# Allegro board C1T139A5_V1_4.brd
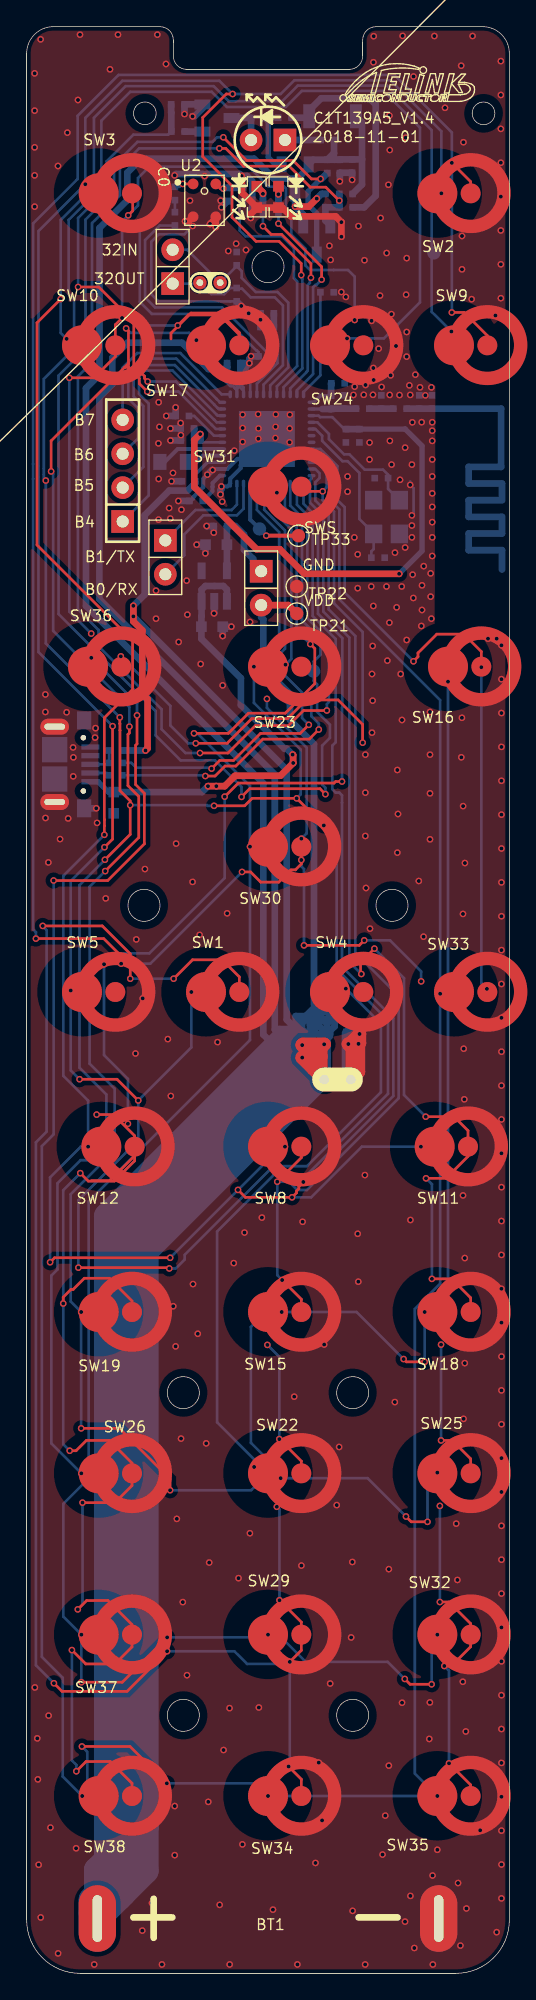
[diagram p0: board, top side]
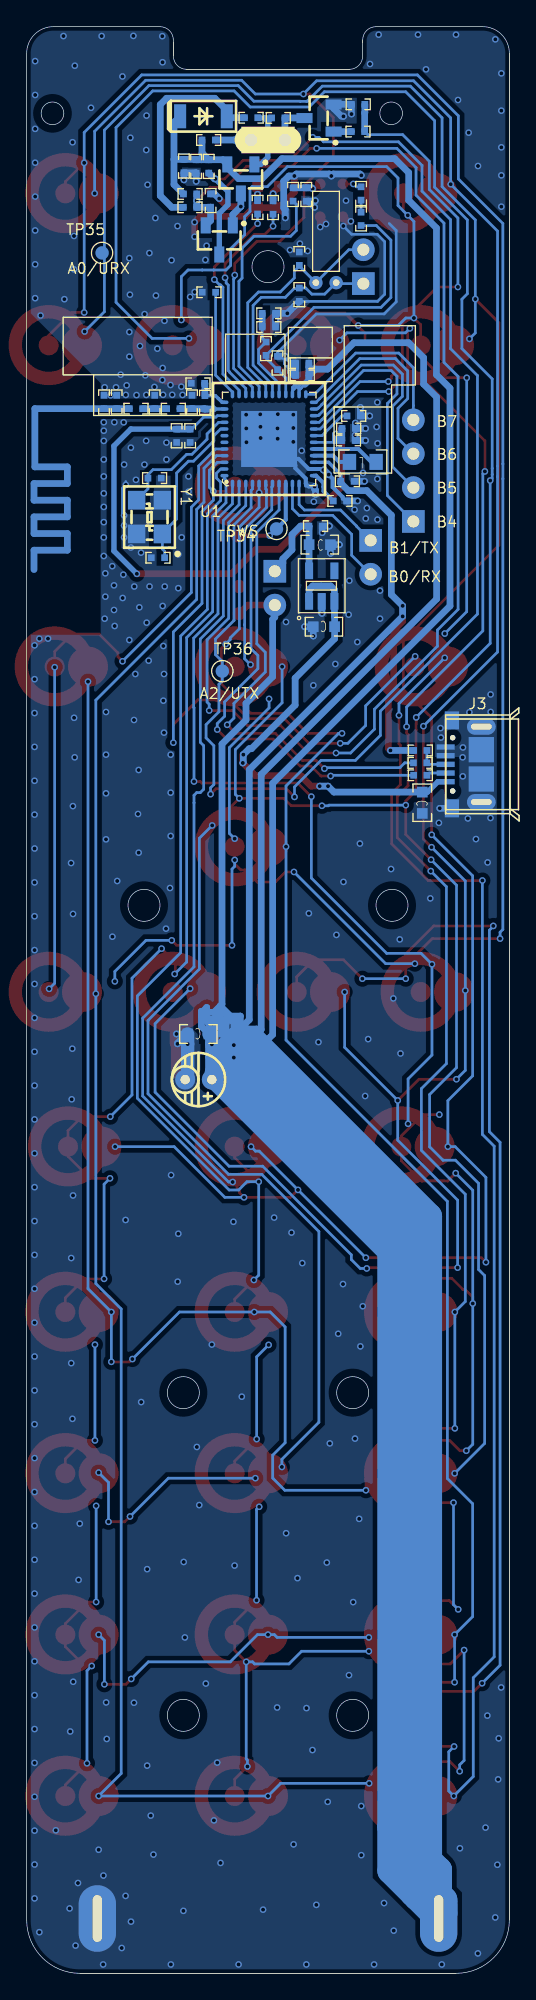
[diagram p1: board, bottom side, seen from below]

Outline 36.2 x 146 mm; copper layers: TOP, BOTTOM. Coordinates in mm from the lower left corner of the outline.
Outline path: circle c8.8,80.1 r1.2 ; circle c8.86,139.5 r0.85 ; circle c11.75,43.55 r1.2 ; circle c11.75,19.35 r1.2 ; circle c18.1,128 r1.2 ; circle c24.45,43.55 r1.2 ; circle c24.45,19.35 r1.2 ; circle c27.4,80.1 r1.2 ; circle c34.26,139.5 r0.85 ; 0,144 0,4 ; 0,144 arc(0.59,145.41) 2,146 10,146 arc(10.71,145.71) 11,145 ; 0,144 0,4 ; 0,4 arc(1.17,1.17) 4,0 ; 4,0 32.2,0 ; 4,0 32.2,0 ; 32.2,0 arc(35.03,1.17) 36.2,4 36.2,144 arc(35.61,145.41) 34.2,146 26.2,146 arc(25.49,145.71) 25.2,145 25.2,144.8 ; 11,145 11,144.8 ; 11,145 11,144.8 ; 11,144.8 11,143.8 arc(11.29,143.09) 12,142.8 ; 12,142.8 24.2,142.8 ; 12,142.8 24.2,142.8 ; 24.2,142.8 arc(24.91,143.09) 25.2,143.8 ; 25.2,144.8 25.2,143.8 ; 25.2,144.8 25.2,143.8

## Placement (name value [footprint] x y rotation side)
BT1  3V_2xAAA  [BAT_2DIP]  18.1 4.11 0 top
C1  0.1uF  [0402]  23.94 115.32 90 bottom
C2  2.2uF  [0402]  24.95 115.32 90 bottom
C4  1uF  [0402]  22.53 126.08 0 bottom
C7  1uF  [0402]  15.53 120.77 180 bottom
C8  1uF  [0402]  12.71 110.43 0 bottom
C10  1uF  [0402]  11.67 116.8 0 bottom
C12  4.7uF  [0402]  24.41 135.55 270 bottom
C13  4.7uF  [0402]  15.23 133.41 270 bottom
C16  10uF  [0603C]  23.33 70.45 0 bottom
C17  10pF  [0402]  17.39 120.78 90 bottom
C18  1uF  [0402]  11.12 133.49 90 bottom
C19  NC  [0402]  26.61 112.14 0 bottom
C20  NC  [0402]  26.35 106.17 180 bottom
C21  NC  [0402]  15.75 128.6 270 bottom
C22  NC  [0402]  15.75 125.9 90 bottom
C23  10pF  [0402]  18.04 123.48 180 bottom
C24  1uF  [0402]  18.04 124.5 180 bottom
C25  1uF  [0402]  12.06 114.96 180 bottom
C26  0.1uF  [0402]  23.49 135.52 270 bottom
C27  1uF  [0402]  12.14 111.91 0 bottom
C28  1uF  [0402]  15.53 119.84 180 bottom
C29  0.1uF  [0402]  12.05 115.86 0 bottom
C30  2.7pF  [0402C]  23.8 117.85 270 bottom
C31  18pF  [0402]  23.35 119.25 0 bottom
C32  2.2pF  [0402C]  26.6 117.85 270 bottom
C33  220pF  [0402C]  25.2 117.35 0 bottom
C34  1.5pF  [0402C]  29.45 117.85 270 bottom
C35  1.2pF  [0402]  30.4 117.85 270 bottom
C39  NC/10uF  [0603C]  13.9 101 0 bottom
C40  NC/10uF  [0603C]  14.22 107.15 180 bottom
C41  NC/0.1uF  [0402]  14.53 108.54 180 bottom
C42  NC/10uF  [0603C]  6.53 87.79 270 bottom
CD1  220uF/10V  [CD2P0_4P0B]  23.31 67.03 0 bottom
D1  Red_LED  [0603-LED]  17.25 133.23 270 top
D2  Red_LED  [0603-LED]  18.89 133.23 270 top
D4  1N4148  [SOD80]  22.94 139.28 180 bottom
D5  LED  [LED_TH_2P54MM_2PIN]  18.1 137.5 0 top
J3  NC/USB_MiniABF  [MICROUSB_DIP]  4.78 89.37 90 bottom
J5  NC/HEADER 4  [HDR254F-1X4X850]  7.2 116.51 270 top
J9  NC/HEADER 2  [HDR254F-1X2X850]  10.4 104.93 90 top
J10  HEADER 2  [HDR254F-1X2X850]  10.95 129.27 270 top
J36  NC/2PIN  [HDR254F-1X2X850]  17.59 102.62 90 top
L3  47UH  [0805L]  10.99 113.36 0 bottom
L4  1.3nH  [0402C]  22.83 117.82 270 bottom
L7  1.5nH  [0402C]  28 117.35 0 bottom
Q2  C1815  [SOT-23]  14.27 139.15 90 bottom
Q3  A1015  [SOT-23]  20.14 134.58 0 bottom
Q4  C1815  [SOT-23]  21.76 130 0 bottom
R1  1K  [0402]  18.88 132.45 90 bottom
R2  1K  [0402]  17.72 132.44 90 bottom
R3  0R  [0402]  16.22 133.41 90 bottom
R4  NC/1.5K  [0402]  6.68 91.71 0 bottom
R7  1  [0402]  22.55 137.5 0 bottom
R8  NC  [0402]  11.34 140.17 180 bottom
R9  100  [0402]  11.35 138.13 0 bottom
R10  10K  [0402]  22.54 135.52 90 bottom
R11  10K  [0402]  22.41 132.96 90 bottom
R12  NC  [0402]  23.94 133.45 180 bottom
R13  47K  [0402]  23.95 132.45 180 bottom
R14  22K  [0402]  19.37 139.17 0 bottom
R15  10K  [0402]  17.33 139.16 0 bottom
R16  NC  [0402]  18.25 121.85 90 bottom
R17  000R  [0402]  11.12 131.59 90 bottom
R69  NC/33  [0402]  6.69 90.79 180 bottom
R70  NC/33  [0402]  6.68 89.86 180 bottom
SW1  SW2PIN  [SW_OUT6_IN3]  13.45 73.6 180 top
SW2  SW2PIN  [SW_OUT6_IN3]  30.8 133.5 180 top
SW3  SW2PIN  [SW_OUT6_IN3]  5.4 133.5 180 top
SW4  SW2PIN  [SW_OUT6_IN3]  22.75 73.6 180 top
SW5  SW2PIN  [SW_OUT6_IN3]  4.15 73.6 180 top
SW8  SW2PIN  [SW_OUT6_IN3]  18.1 62 180 top
SW9  SW2PIN  [SW_OUT6_IN3]  32.05 122.1 180 top
SW10  SW2PIN  [SW_OUT6_IN3]  4.15 122.1 180 top
SW11  SW2PIN  [SW_OUT6_IN3]  30.6 62 180 top
SW12  SW2PIN  [SW_OUT6_IN3]  5.6 62 180 top
SW15  SW2PIN  [SW_OUT6_IN3]  18.1 49.6 180 top
SW16  SW2PIN  [SW_OUT6_IN3]  31.6 98 180 top
SW17  SW2PIN  [SW_OUT6_IN3]  13.45 122.1 180 top
SW18  SW2PIN  [SW_OUT6_IN3]  30.8 49.6 180 top
SW19  SW2PIN  [SW_OUT6_IN3]  5.4 49.6 180 top
SW22  SW2PIN  [SW_OUT6_IN3]  18.1 37.5 180 top
SW23  SW2PIN  [SW_OUT6_IN3]  18.1 98 180 top
SW24  SW2PIN  [SW_OUT6_IN3]  22.75 122.1 180 top
SW25  SW2PIN  [SW_OUT6_IN3]  30.8 37.5 180 top
SW26  SW2PIN  [SW_OUT6_IN3]  5.4 37.5 180 top
SW29  SW2PIN  [SW_OUT6_IN3]  18.1 25.4 180 top
SW30  SW2PIN  [SW_OUT6_IN3]  18.1 84.5 180 top
SW31  SW2PIN  [SW_OUT6_IN3]  18.1 111.5 180 top
SW32  SW2PIN  [SW_OUT6_IN3]  30.8 25.4 180 top
SW33  SW2PIN  [SW_OUT6_IN3]  32.05 73.6 180 top
SW34  SW2PIN  [SW_OUT6_IN3]  18.1 13.3 180 top
SW35  SW2PIN  [SW_OUT6_IN3]  30.8 13.3 180 top
SW36  SW2PIN  [SW_OUT6_IN3]  4.6 98 180 top
SW37  SW2PIN  [SW_OUT6_IN3]  5.4 25.4 180 top
SW38  SW2PIN  [SW_OUT6_IN3]  5.4 13.3 180 top
TP21  VDD  [TP100]  20.26 101.98 0 top
TP22  GND  [TP100]  20.26 104.01 0 top
TP33  SWS  [TP100]  20.38 107.82 0 top
TP34  SWS  [TP100]  17.46 108.33 180 bottom
TP35  URX  [TP100]  30.54 129.03 180 bottom
TP36  UTX  [TP100]  21.53 97.66 180 bottom
U1  TLSR8258F512ET48  [QFN_7X7_48PIN_0P5_4P20X4P20]  18.02 115.08 90 bottom
U2  GA-BFA423-A83-1  [GA_BFA423_A83]  13.33 132.97 0 top
U5  NC/XC6219_3.3V_SOT-23-5  [SOT-23-5]  14.07 104.04 180 bottom
Y1  24MHz-12pF-+/-20ppm  [OSCCC250X320X110]  26.99 109.22 0 bottom
Y2  NC/32.768KHz - 9pf - +/-20ppm  [OSC_2X6]  13.75 130.8 270 bottom

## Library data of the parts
BT1 = BATTERY_2xAAA_3V
C1 C26 C41 = C1005X5R1C104K
C2 = C1005X5R1A225K
C4 C8 = C1005X5R1C105K
C7 = C1608X5R1C105M_0
C10 = C1005X5R1C105K_0
C12 = C1608X5R1A226M
C13 C17 C18 C23-C25 = C1608X5R0J475M
C16 = C1608X5R0J106M
C19-C22 C30 C32-C34 = C1608_NC
C27 C29 = C1005X5R1C105K_1
C28 = C1005X5R1C105K_2
C31 = C1005C0G1H100D
C35 = C1005_NC
C39 C40 C42 = C1608X5R1A106K
CD1 = CD_220uF_16V
D1 D2 = 0603D_Red
D4 = Diode_1N4148
D5 = Led_Th_3mm_1: User Part Number: partnum; Tolerance: RichardLC
J3 = USB_MiniABF_2
J5 = HEADER 4: User Part Number: pn; Tolerance: RichardLC
J9 J10 = HEADER 2: User Part Number: pn; Tolerance: RichardLC
J36 = B2S_2: User Part Number: pn; Tolerance: RichardLC
L3 = IND_0
L4 L7 = MLK1608_000R
Q2 Q4 = NPN_C1815
Q3 = PNP_A1015
R1-R4 R16 R17 = RS0402K472JT
R7 = RS0805K1R0JT
R8 R12 = RS0402_NC
R9 = RS0402K101JT
R10 R11 R15 = RS0402K103JT
R13 = RS0402K473JT
R14 = RS0402K223JT
R69 R70 = RS0402K330JT
SW1-SW5 SW8-SW12 SW15-SW19 SW22-SW26 SW29-SW38 = SW2PIN_0
TP21 TP22 TP33-TP36 = TestPad100
U1 = TLSR8258F512ET48
U2 = MULPS4CX-RM5_0
U5 = XC6219_1.3V_SOT-23-5
Y1 = CRYSTAL4/SM_0: Tolerance: RichardLC
Y2 = OSC_2x6_2pin_16Mhz

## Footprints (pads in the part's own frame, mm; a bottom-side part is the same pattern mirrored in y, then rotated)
0402
  rect 0.5x0.5 smd: 1(-0.5,0) 2(0.5,0)
0402C
  rect 0.5x0.5 smd: 1(-0.5,0) 2(0.5,0)
0603-LED
  rect 0.8x0.8 smd: A(-0.8,0) C(0.8,0)
0603C
  rect 0.8x0.8 smd: 1(-0.8,0) 2(0.8,0)
0805L
  rect 1x1.2 smd: 1(-1,0) 2(1,0)
BAT_2DIP
  oval 2.8x5 hole 0.7x3.5: 1(-12.8,0) 2(12.8,0)
CD2P0_4P0B
  round 1.5 hole 0.7: 1(-1,0) 2(1,0)
GA_BFA423_A83
  round 0.8 smd: 1(-0.85,1.23) 2(-0.85,-1.23) 3(0.85,-1.23) 4(0.85,1.23)
HDR254F-1X2X850
  rect 1.7x1.7 hole 0.9: 1(2.54,0)
  round 1.7 hole 0.9: 2(0,0)
HDR254F-1X4X850
  rect 1.7x1.7 hole 0.9: 1(7.62,0)
  round 1.7 hole 0.9: 2(5.08,0) 3(2.54,0) 4(0,0)
LED_TH_2P54MM_2PIN
  rect 1.7x1.7 hole 0.9: A(1.27,0)
  round 1.7 hole 0.9: C(-1.27,0)
MICROUSB_DIP
  round 0.4 hole 0.6 unplated: (-0.7,-0.525) (3.3,-0.525)
  rect 0.4x1.35 smd: 1(0,0) 2(0.65,0) 3(1.3,0) 4(1.95,0) 5(2.6,0)
  oval 1.2x2.15 hole 0.45x1.55: 6(-1.525,-2.675) 7(4.125,-2.675)
  rect 1.9x1.9 smd: 8(0.2,-2.675) 9(2.4,-2.675)
  rect 1.35x1.07 smd: 10(-1.996,-0.468) 11(4.596,-0.468)
OSC_2X6
  round 1 hole 0.5: 1(4,0.76) 2(4,-0.76)
OSCCC250X320X110
  rect 1.3x1.4 smd: 1(-0.965,1.265) 2(-0.965,-1.265) 3(0.965,-1.265) 4(0.965,1.265)
QFN_7X7_48PIN_0P5_4P20X4P20
  oval 0.6x0.26 smd: 1(-3.35,2.75) 2(-3.35,2.25) 3(-3.35,1.75) 4(-3.35,1.25) 5(-3.35,0.75) 6(-3.35,0.25) 7(-3.35,-0.25) 8(-3.35,-0.75) 9(-3.35,-1.25) 10(-3.35,-1.75) 11(-3.35,-2.25) 12(-3.35,-2.75) 25(3.35,-2.75) 26(3.35,-2.25) 27(3.35,-1.75) 28(3.35,-1.25) 29(3.35,-0.75) 30(3.35,-0.25) 31(3.35,0.25) 32(3.35,0.75) 33(3.35,1.25) 34(3.35,1.75) 35(3.35,2.25) 36(3.35,2.75)
  oval 0.26x0.6 smd: 13(-2.75,-3.35) 14(-2.25,-3.35) 15(-1.75,-3.35) 16(-1.25,-3.35) 17(-0.75,-3.35) 18(-0.25,-3.35) 19(0.25,-3.35) 20(0.75,-3.35) 21(1.25,-3.35) 22(1.75,-3.35) 23(2.25,-3.35) 24(2.75,-3.35) 37(2.75,3.35) 38(2.25,3.35) 39(1.75,3.35) 40(1.25,3.35) 41(0.75,3.35) 42(0.25,3.35) 43(-0.25,3.35) 44(-0.75,3.35) 45(-1.25,3.35) 46(-1.75,3.35) 47(-2.25,3.35) 48(-2.75,3.35)
  rect 4.2x4.2 smd: 49(0,0)
SOD80
  rect 0.9x1.8 smd: A(-1.75,0) C(1.75,0)
SOT-23
  rect 0.75x1.2 smd: 1(-1.016,-1.092) 2(1.016,-1.092) 3(0,1.092)
SOT-23-5
  rect 0.6x1.25 smd: 1(-0.95,-1.145) 2(0,-1.145) 3(0.95,-1.145) 4(0.95,1.145) 5(-0.95,1.145)
SW_OUT6_IN3
  round 3 smd: 1(0,0)
  custom 1.5x1.5 smd: 2(-2.5,0)
TP100
  round 1 smd: 1(0,0)

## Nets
GND: BT1.2(-) C1.1 C2.1 C4.2 C7.1 C8.1 C10.1 C12.2 C13.2 C16.2 C17.2 C19.1 C20.1 C21.1 C22.1 C23.2 C24.2 C25.2 C26.2 C27.1 C28.1 C29.1 C30.1 C31.2 C32.1 C34.1 C35.1 C39.2 C40.2 C41.2 C42.2 CD1.2 D1.C(CATHODE) D2.C(CATHODE) J3.4(ID) J3.5(GND) J3.6(S1) J3.7(S2) J3.8(S3) J3.9(S4) J3.10(S5) J3.11(S6) Q2.2(E) R8.1 TP22.1(TP) U1.12(DVSS#12) U1.14(DVSS#14) U1.49(GND) U2.2(GND#2) U2.3(GND#3) U5.2(VSS) Y1.2 Y1.4
VDD1V2: C1.2 C2.2 C25.1 C29.2 U1.18(VDD1V2) U1.39(AVDD1V2)
TL_32INPUT: C21.2 J10.2 U1.31(P1/URX/I2CCK/32KI/PGAN1/C[3]) Y2.2
TL_32OUTPUT: C22.2 J10.1 U1.30(P0/7816TRX/I2CSDA/32KO/PGAP1/C[) Y2.1
TL_AMICBIAS: R3.1 U1.32(P2/UCTS/P0N/BIAS/C[4])
TL_AMICSN: C23.1 C24.1 R16.2 U1.29(I2CCK/P1N/P0/PGAN0/C[1])
TL_AMICSP: C17.1 R16.1 R17.1 U1.28(I2CSDA/P4N/URTS/PGAP0/C[0])
TL_B0: J9.2 U1.10(P3/URX/ATSEL1/B[0])
TL_B1: J9.1 U1.11(P4/UTX/ATSEL2/B[1])
TL_B4: J5.1 U1.22(SDMP0/P4/B[4])
TL_B5: J5.2 U1.23(SDMN0/P5/B[5])
TL_B6: J5.3 U1.24(SDMP1/DI/URTS/B[6])
TL_B7: J5.4 U1.25(SDMN1/DO/URX/B[7])
TL_COL0: SW1.1 SW2.1 SW3.1 SW4.1 SW5.1 U1.33(P3N/URX/ATSEL0/C[5])
TL_COL1: SW8.1 SW9.1 SW10.1 SW11.1 SW12.1 TP35.1(TP) U1.2(DMIC_DI/P0N/URX/A[0])
TL_COL2: SW15.1 SW16.1 SW17.1 SW18.1 SW19.1 U1.20(P5/UCTS/CYC2LNA/B[2])
TL_COL3: SW22.1 SW23.1 SW24.1 SW25.1 SW26.1 U1.6(CK/URTS/P2/A[4])
TL_COL4: SW29.1 SW30.1 SW31.1 SW32.1 SW37.1 U1.5(DI/UCTS/P1/A[3])
TL_COL5: SW33.1 SW34.1 SW35.1 SW36.1 SW38.1 U1.45(P1N/I2SSDI/7816TRX/D[3])
TL_DM: R70.1 U1.7(DM/A[5])
TL_DP: R69.1 U1.8(DP/A[6])
TL_IRCONTROL: Q4.2(E) R11.1 R12.2 R13.2 U1.3(DMIC_CK/7816CLK/I2SCK/A[1])
TL_IRIN: Q4.3(C) R10.1 TP36.1(TP) U1.4(DO/UTX/P0/A[2])
TL_IROUT: R8.2 R9.1 U1.21(P0N/URTS/CYC2PA/B[3])
TL_LED1: R2.1 U1.34(CYC2LNA/ATSEL1/P4N/C[6])
TL_LED2: R1.1 U1.35(CYC2PA/ATSEL2/P5N/C[7])
TL_ROW0: SW1.2 SW8.2 SW15.2 SW22.2 SW29.2 SW34.2 U1.47(P0/P0N/D[5])
TL_ROW1: SW2.2 SW9.2 SW16.2 SW23.2 SW30.2 SW33.2 U1.44(CN/I2SLR/P3/D[2])
TL_ROW2: SW3.2 SW10.2 SW17.2 SW24.2 SW31.2 SW36.2 U1.46(SWM/I2SSDO/P2N/D[4])
TL_ROW3: SW4.2 SW11.2 SW18.2 SW25.2 SW32.2 SW35.2 U1.48(CN/URX/ATSEL0/D[6])
TL_ROW4: SW5.2 SW12.2 SW19.2 SW26.2 SW37.2 SW38.2 U1.1(CK/I2SBCK/7816TRX/D[7])
TL_RST: C4.1 U1.36(RESETB)
TL_SWS: TP33.1(TP) TP34.1(TP) U1.9(SWS/URTS/A[7])
TL_VBUS: C39.1 C42.1 J3.1(V_BUS) U5.1(VIN) U5.3(CE)
TL_VDD: BT1.1(+) C7.2 C12.1 C16.1 C26.1 C27.2 C28.2 CD1.1 D4.A J36.2 Q3.2(E) R4.2 R7.2 R10.2 R12.1 TP21.1(TP) U1.15(VDD_IO) U1.26(VDD3) U1.27(VDDIO_AMS)
TL_XC1: C19.2 U1.40(XC1) Y1.3
TL_XC2: C20.2 U1.41(XC2) Y1.1
N21000893: D2.A(ANODE) R1.2
N21007782: D1.A(ANODE) R2.2
N21036936: C13.1 R3.2 U2.4(VDD)
N21036981: C18.1 R17.2
N21036983: C18.2 U2.1(OUTPUT)
N21081547: C40.1 C41.1 J36.1 U5.5(VOUT)
N21081898: J3.3(D+) R4.1 R69.2
N21081900: J3.2(D-) R70.2
N21088560: C10.2 U1.19(VDD_F)
N21088582: L3.1 U1.17(VDCDC)
N21088586: L3.2 U1.16(VDCDC_SW)
N21088616: C8.2 U1.13(VDD1V)
N21092386: C30.2 C33.1 L4.2 U1.38(ANT)
N21092388: C31.1 L4.1 U1.37(VANT)
N21092398: C32.2 C33.2 L7.1
N21092424: C34.2 C35.2 L7.2
N21108187: D5.A(ANODE) R7.1
N21108227: D4.C R13.1 R14.2
N21108333: Q2.1(B) R9.2
N21108349: D5.C(CATHODE) Q2.3(C) R15.1
N21108369: Q3.3(C) Q4.1(B) R11.2
N21108379: Q3.1(B) R14.1 R15.2

Pads without a net: U1 42 43; U5 4

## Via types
v1: diameter 0.5, hole 0.3, TOP to BOTTOM, 547 vias

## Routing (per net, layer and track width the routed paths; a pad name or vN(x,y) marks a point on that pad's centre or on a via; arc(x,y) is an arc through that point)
GND: length 124.3
  TOP w0.5: v1(13.75,131.2) 14.18,131.63 ; 14.18,131.63 v1(14.18,130.98) ; 14.18,131.63 U2.3 ; v1(23.61,130.24) v1(23.61,131.34) 23.18,131.77 19.84,131.77 19.17,132.43 D2.C D1.C ; v1(16.8,131.66) 16.8,131.93 17.25,132.39 D1.C ; v1(11.88,131.4) 12.14,131.4 U2.2 ; D1.C 17.25,132.45 16.12,133.58 v1(16.12,134.8)
  TOP w1: 24.41,67.13 24.89,67.61 v1(24.89,69.71) 24.97,69.79 v1(24.97,70.45) 24.21,69.7 v1(24.13,69.7) 24.41,69.41 24.41,67.13 ; 24.41,67.13 CD1.2
  BOTTOM w0.2: U1.49 18.1,115.15 v1(18.66,115.15) ; U1.49 17.2,114.86 v1(16.2,114.86) ; U1.49 17.45,115.87 v1(17.39,115.87) ; U1.49 19.57,115.7 v1(19.73,115.87) ; U1.49 18.02,116.28 v1(17.36,116.94) ; U1.49 16.85,116.9 v1(16.2,116.9) ; U1.49 19.21,114.83 v1(19.72,114.83) ; U1.49 18.67,115.85 v1(18.67,115.99) ; U1.49 19.6,116.9 v1(19.74,116.9) ; U1.49 18.64,116.88 v1(18.68,116.92) ; C17.2 17.39,121.59 17.25,121.73 17.21,121.73 14.49,124.45 9.39,124.45 8.48,125.36 8.48,130.71 9.01,131.24 ; 28.77,111.89 v1(28.77,111.63) 29.02,111.38 29.02,109.47 v1(28.89,109.35) ; v1(12.45,131.05) 11.83,130.43 9.91,130.43 9.35,129.87 9.35,125.93 9.89,125.4 15.27,125.4 15.27,125.4 C22.1
  BOTTOM w0.25: 14.08,112.83 13.95,112.7
  BOTTOM w0.3: 16.52,113.58 U1.49 ; 16.52,113.58 15.81,113.58 15.05,112.83 U1.14 14.03,112.83 v1(13.95,112.75) ; 16.52,113.58 16.05,113.11 16.05,112.89 15.27,112.1 U1.12 15.05,111.51 v1(14.6,111.51) ; 12.49,110.59 12.49,110.72 13.24,111.46 13.24,112.09 v1(13.55,112.4)
  BOTTOM w0.5: v1(24.89,69.71) 24.89,69.75 24.19,70.45 ; 15.06,132.91 14.59,132.91 v1(14.55,132.95) ; 15.06,132.91 C13.2 ; 15.06,132.91 v1(14.6,132.45) ; v1(14.03,108.05) C41.2 13.51,108.54 v1(13.5,108.55) ; v1(14.7,100.3) 14.7,100.3 C39.2 15.35,101 v1(15.35,101) ; 16.41,120.11 16.03,120.48 ; 16.41,120.11 16.41,120.47 v1(16.7,120.76) ; 16.41,120.11 16.14,119.84 C28.1 16.03,120.48 ; 16.03,120.48 C7.1 16.69,120.77 v1(16.7,120.76) ; v1(14.6,111.51) 14.6,111.3 14.53,111.23 v1(14.53,110.92) ; v1(10.78,114.96) C25.2 v1(11.56,115.36) ; v1(12.75,107.15) 12.75,107.15 C40.2 13.42,106.52 v1(13.4,106.5) ; v1(12.44,139.27) 12.46,139.29 12.6,139.29 13.18,139.87 Q2.2 13.17,140.17 R8.1 v1(11.84,139.45) ; v1(5.22,87.38) J3.10 ; U5.2 14.07,102.02 v1(14.05,102) ; 24.19,70.45 v1(24.97,70.45) ; 24.19,70.45 C16.2 ; v1(13.95,112.75) 13.9,112.75 v1(13.55,112.4) ; v1(24.41,134.51) C12.2 23.52,135.05 C26.2 v1(23.49,134.4) ; v1(10.78,115.86) C29.1 v1(11.55,116.27) ; C8.1 v1(11.38,110.43) ; v1(11.1,134.85) 11.2,134.95 13.2,134.95 v1(13.35,134.8) 13.5,134.95 15.97,134.95 v1(16.12,134.8) 16.53,134.8 16.92,134.41 16.92,132.41 16.8,132.29 v1(16.8,131.66) ; v1(11.17,117.44) C10.1 v1(10.47,116.8) ; v1(16.7,120.76) 16.7,121.08 16.89,121.28 C17.2 ; C23.2 v1(17.54,124.02) C24.2 v1(16.65,124.5) v1(16.1,125.05) C22.1 ; C27.1 v1(10.86,111.91)
  BOTTOM w1: C16.2 v1(24.13,69.7) 24.13,67.22 CD1.2
  vias: v1(0.6,142.5) v1(0.6,139.7) v1(0.6,136.95) v1(0.6,134.85) v1(0.6,132.5) v1(0.62,21.44) v1(0.8,17.62) v1(0.84,14.55) v1(0.9,8.14) v1(1.05,145.05) v1(1.06,4.19) v1(1.4,95.92) v1(1.4,94.6) v1(1.41,86.65) v1(1.63,83.32) v1(1.65,19.33) v1(1.78,10.93) v1(2.35,135.55) v1(2.36,1.5) v1(2.5,85.07) v1(3,94.58) v1(3.05,138.05) v1(3.11,86.62) v1(3.48,91.94) v1(3.5,91.2) v1(3.49,89.77) v1(3.71,9.38) v1(3.85,140.5) v1(4,145.4) v1(5.13,92.68) v1(5.07,0.67) v1(5.16,93.39) v1(5.28,86.28) v1(5.93,80.62) v1(6.25,142.8) v1(6.85,145.4) v1(8.22,77.54) v1(8.16,68.99) v1(8.7,73.12) v1(8.67,3.2) v1(8.87,82.82) v1(9.4,5.27) v1(9.7,103.7) v1(9.7,101.6) v1(9.8,145.4) v1(9.9,117.83) v1(9.88,114.75) v1(9.9,112.08) v1(9.89,109.03) v1(9.96,115.98) v1(10.15,0.67) v1(10.45,143.2) v1(10.59,70.07) v1(10.68,109.89) v1(10.77,109.11) v1(10.81,65.8) v1(10.97,112.53) v1(10.99,50.03) v1(11.1,12.55) v1(11.1,8.86) v1(11.21,84.73) v1(11.17,47.02) v1(11.26,34.09) v1(11.4,99.85) v1(11.61,109.77) v1(11.58,40.11) v1(11.71,27.84) v1(12,104.45) v1(12.03,22.36) v1(12.05,101.9) v1(12.25,132.95) v1(12.44,81.86) v1(12.48,51.69) v1(12.83,47.97) v1(12.97,77.88) v1(13.05,98.2) v1(13.46,39.75) v1(13.62,12.86) v1(13.69,30.81) v1(14.32,69.84) v1(14.47,5.14) v1(14.66,110.38) v1(14.7,96.6) v1(14.77,16.75) v1(15.04,79.5) v1(15.12,129.18) v1(15.22,19.89) v1(15.23,0.67) v1(15.53,53.27) v1(15.57,114.2) v1(15.71,129.73) v1(15.89,29.64) v1(16.2,115.9) v1(16.18,9.67) v1(16.34,55.56) v1(16.45,129.25) v1(16.74,33.01) v1(16.83,121.28) v1(16.75,101.35) v1(17.38,115.09) v1(17.42,19.94) v1(17.64,56.68) v1(18.47,4.78) v1(20.07,43.25) v1(20.31,0.67) v1(20.61,30.58) v1(20.7,56.37) v1(21.66,8.28) v1(21.91,15.8) v1(22.16,11.47) v1(22.31,47.16) v1(22.71,129.56) v1(22.8,128.51) v1(22.76,21.73) v1(23.26,35.12) v1(23.44,39.48) v1(23.6,126.1) v1(23.94,125.73) v1(24.07,112.27) v1(24.07,111.12) v1(24.33,25.19) v1(24.42,30.85) v1(24.45,4.69) v1(24.51,118.38) v1(24.6,119) v1(24.57,107.7) v1(24.83,106.43) v1(24.83,103.89) v1(24.83,55.47) v1(24.89,131.04) v1(24.87,51.87) v1(25.33,128.48) v1(25.28,118.39) v1(25.41,119.13) v1(25.4,91.4) v1(25.4,88.55) v1(25.4,85.3) v1(25.45,81.4) v1(25.37,59.87) v1(25.39,0.67) v1(25.72,114.81) v1(25.72,113.54) v1(25.84,104.01) v1(25.75,78.35) v1(25.87,123.94) v1(25.95,99.55) v1(25.9,97.45) v1(25.95,95.45) v1(25.9,93.05) v1(26.03,145.28) v1(26.01,143.33) v1(26,120.4) v1(26.02,119.5) v1(25.97,118.39) v1(26,102.55) v1(26.4,121.85) v1(26.55,131.65) v1(26.5,125.83) v1(26.62,118.98) v1(26.69,8.91) v1(26.89,11.83) v1(27,129.02) v1(26.99,104.01) v1(27.13,134.14) v1(27.05,98.45) v1(27.21,139.33) v1(27.23,136.75) v1(27.23,118.38) v1(27.24,114.94) v1(27.2,101.3) v1(27.16,30.31) v1(27.16,15.58) v1(27.3,119.85) v1(27.36,124.44) v1(27.37,113.16) v1(27.62,106.55) v1(27.61,42.85) v1(27.7,122.05) v1(27.75,102.45) v1(27.8,90.25) v1(27.8,84.05) v1(27.85,86.95) v1(27.96,118.37) v1(28,112.01) v1(28.13,104.01) v1(28.05,97.45) v1(28.15,94) v1(28.2,145.31) v1(28.15,20.3) v1(28.42,137.67) v1(28.38,114.43) v1(28.38,106.93) v1(28.38,3.88) v1(28.5,128.64) v1(28.46,125.9) v1(28.5,123.1) v1(28.5,121.25) v1(28.5,100) v1(28.7,119.1) v1(28.77,118.38) v1(28.78,56.5) v1(28.78,5.81) v1(28.92,116.33) v1(28.89,113.16) v1(28.89,108.58) v1(28.89,107.7) v1(28.95,104.9) v1(29.02,142.26) v1(29,103.15) v1(29.15,119.9) v1(29.07,1.9) v1(29.41,81.93) v1(29.5,118.95) v1(29.62,116.34) v1(29.65,104.1) v1(29.65,102.25) v1(29.6,101.05) v1(29.78,105.54) v1(29.77,77.75) v1(29.9,118.35) v1(30.25,94.6) v1(30.25,91.4) v1(30.25,88.5) v1(30.25,85.05) v1(30.24,20.32) v1(30.2,17.58) v1(30.3,105) v1(30.3,103.25) v1(30.35,118.95) v1(30.42,116.33) v1(30.42,115.7) v1(30.42,114.94) v1(30.42,113.54) v1(30.42,112.27) v1(30.42,111) v1(30.42,109.98) v1(30.42,108.84) v1(30.42,107.7) v1(30.42,106.3) v1(30.35,101.6) v1(30.44,7.34) v1(30.47,0.67) v1(30.58,145.3) v1(30.8,9.27) v1(31.38,139.92) v1(32.22,33.73) v1(32.31,29.5) v1(32.35,6.77) v1(32.53,2.08) v1(32.59,143.07) v1(32.65,130.3) v1(32.65,127.8) v1(32.64,94.17) v1(32.6,91.2) v1(32.73,87.54) v1(32.72,79.45) v1(32.72,58.34) v1(32.71,21.87) v1(32.76,137.33) v1(32.78,69.35) v1(32.82,65.55) v1(32.77,41.59) v1(32.87,83.27) v1(32.86,53.65) v1(32.86,45.77) v1(32.94,18.14) v1(32.98,4.86) v1(33.44,145.3) v1(33.37,125.56) v1(34.01,10.73) v1(34.6,100.1) v1(35.16,124.34) v1(35.25,100.1) v1(35.25,3.09) v1(35.56,143.42) v1(35.56,140.88) v1(35.56,138.34) v1(35.56,135.8) v1(35.56,133.26) v1(35.56,130.72) v1(35.56,128.18) v1(35.56,125.64) v1(35.61,99.6) v1(35.61,97.06) v1(35.61,94.52) v1(35.61,91.98) v1(35.61,89.44) v1(35.61,86.9) v1(35.61,84.36) v1(35.61,81.82) v1(35.61,79.28) v1(35.61,76.74) v1(35.61,74.2) v1(35.61,71.66) v1(35.61,69.12) v1(35.61,66.58) v1(35.61,64.04) v1(35.61,61.5) v1(35.61,58.96) v1(35.61,56.42) v1(35.61,53.88) v1(35.61,51.34) v1(35.61,48.8) v1(35.61,46.26) v1(35.61,43.72) v1(35.61,41.18) v1(35.61,38.64) v1(35.61,36.1) v1(35.61,33.56) v1(35.61,31.02) v1(35.61,28.48) v1(35.61,25.94) v1(35.61,23.4) v1(35.61,20.86) v1(35.61,18.32) v1(35.61,15.78) v1(35.61,13.24) v1(35.61,10.7) v1(35.61,8.16) v1(35.61,5.62)
VDD1V2: length 45.3
  TOP w0.5: v1(13.02,115.44) 12.57,115 12.57,111.48 17.24,106.81 18.99,106.81 20.83,104.96 v1(27.94,104.96)
  BOTTOM w0.2: 13.04,114.96 13.18,114.83 U1.18 ; U1.39 21.89,116.83 22.01,116.71 22.92,116.71 23.82,115.82 C1.2
  BOTTOM w0.4: C2.2 28.38,115.82 28.38,115.82 29.65,114.55 29.65,106.68 v1(27.94,104.96)
  BOTTOM w0.5: v1(13.02,115.44) 13.04,115.42 13.04,114.96 C25.1 12.56,114.96 12.56,115.85 C29.2 ; C1.2 C2.2
TL_32INPUT: length 19.1
  BOTTOM w0.2: 15.75,128.04 Y2.2 12.04,129.27 J10.2 ; 15.75,128.04 16.13,127.66 16.13,127.15 17.18,126.1 18.81,126.1 19.62,125.3 19.62,120.44 18.27,119.09 U1.31 ; 15.75,128.04 C21.2
TL_32OUTPUT: length 16.7
  BOTTOM w0.2: U1.30 17.77,119.16 19.22,120.61 19.22,125.09 18.61,125.7 16.8,125.7 16.15,126.35 15.8,126.35 C22.2 15.27,126.4 14.81,125.94 13.85,125.94 Y2.1 12.92,126.73 J10.1
TL_AMICBIAS: length 18.6
  BOTTOM w0.2: U1.32 18.77,119.02 20.28,120.54 20.28,126.9 20.04,127.14 20.04,129.39 19.15,130.28 16.41,130.28 15.98,130.71 15.98,132.67 R3.1
TL_AMICSN: length 7.1
  BOTTOM w0.2: C23.1 18.54,122.64 R16.2 18.81,121.79 18.81,120.76 17.27,119.22 U1.29
  BOTTOM w0.5: C24.1 C23.1
TL_AMICSP: length 21.7
  BOTTOM w0.2: U1.28 16.77,119.66 C17.1 18.25,121.14 R16.1 14.66,124.94 9.63,124.94 8.88,125.69 8.88,129.99 9.98,131.09 R17.1
TL_B0: length 10.7
  BOTTOM w0.2: U1.10 16.27,109.85 15.77,109.35 13.25,109.35 11.82,107.92 11.82,106.35 J9.2
TL_B1: length 8.1
  BOTTOM w0.2: U1.11 15.77,110.15 15.37,109.75 12.66,109.75 11.45,108.54 11.45,108.52 J9.1
TL_B4: length 19.8
  BOTTOM w0.2: J5.1 9.15,110.84 9.15,117.73 8.43,118.46 8.43,119.78 8.86,120.21 10.94,120.21 14.22,116.93 14.22,116.93 14.32,116.83 U1.22
TL_B5: length 17.8
  BOTTOM w0.2: J5.2 8.75,112.98 8.75,117.54 8.02,118.27 8.02,119.94 8.7,120.62 11.11,120.62 14.07,117.66 14.07,117.65 14.32,117.4 14.33,117.4 14.4,117.33 U1.23
TL_B6: length 15.8
  BOTTOM w0.2: J5.3 8.35,115.12 8.35,117.38 7.62,118.11 7.62,120.18 8.55,121.11 11.22,121.11 14.24,118.08 14.24,118.08 14.5,117.83 U1.24
TL_B7: length 13.7
  BOTTOM w0.2: J5.4 7.2,117.59 7.2,117.59 7.2,120.42 8.29,121.52 11.53,121.52 14.62,118.43 U1.25
TL_COL0: length 212.2
  TOP w0.2: v1(23.94,73.85) 23.68,73.6 SW4.1 ; v1(8.37,65.46) 6.78,67.06 v1(3.97,67.06) ; v1(15.44,140.95) 14.97,140.95 13.2,139.19 13.2,136.26 15.4,134.06 15.4,131.7 17.2,129.9 18.93,129.9 20.59,128.23 v1(20.59,127.37) ; v1(6.44,93.54) 6.44,85.07 v1(5.84,84.46) ; SW3.1 4.72,134.18 v1(4.4,134.18) ; v1(3.88,52.93) 10.63,52.93 v1(10.7,52.87) ; SW2.1 v1(31.1,133.5) ; v1(3.3,73.71) 3.42,73.6 SW5.1 ; SW1.1 v1(12.35,73.6)
  BOTTOM w0.2: v1(5.84,84.46) 3.3,81.93 v1(3.3,73.71) 3.3,67.72 v1(3.97,67.06) ; U1.33 19.27,118.96 20.68,120.37 20.68,127.07 20.59,127.16 v1(20.59,127.37) ; v1(23.94,73.85) 26.57,71.22 26.57,66.08 21.02,60.53 18.5,60.53 11.85,53.89 11.85,53.53 11.18,52.87 v1(10.7,52.87) ; v1(12.35,73.6) 12.35,69.45 v1(8.37,65.46) 8.37,62.48 3.88,57.99 v1(3.88,52.93) ; v1(6.44,93.54) 0.89,99.1 0.89,112.25 0.88,112.25 0.88,113.04 0.89,113.04 0.89,130.67 v1(4.4,134.18) 4.4,139.16 7.18,141.94 14.46,141.94 v1(15.44,140.95) 19.05,140.95 20.08,141.98 27.27,141.98 31.1,138.15 v1(31.1,133.5)
TL_COL1: length 245.4
  TOP w0.2: SW10.1 3.48,122.1 v1(2.99,122.58) ; v1(20.75,59.35) 20.41,59.01 20.41,58.85 20.24,58.67 20.24,58.54 v1(19.9,58.2) 16.41,58.2 v1(15.85,58.76) ; SW12.1 v1(4.61,62) ; SW8.1 v1(19.37,62) ; v1(31.85,123.14) 32.05,122.94 SW9.1 ; v1(2.55,125.57) 0.77,123.79 0.77,107.12 7.95,99.95 7.95,96.29 5.83,94.17 5.83,86.52 5.83,86.51 5.83,86.06 5.83,86.05 v1(5.83,85.39) ; v1(1.76,53.33) 2.09,53.67 v1(10.76,53.67) ; SW11.1 v1(29.57,62)
  BOTTOM w0.2: v1(1.76,53.33) 1.76,59.69 4.06,62 v1(4.61,62) 4.61,65.45 2.75,67.31 2.75,82.32 v1(5.83,85.39) ; v1(19.37,62) 19.04,61.66 18.76,61.66 v1(15.85,58.76) v1(10.76,53.67) ; U1.2 20.27,110.15 21.45,108.97 21.45,101.8 23.18,100.07 23.18,92.33 22.92,92.08 22.92,88.81 23.18,88.55 23.45,88.55 23.65,88.35 23.65,87.8 23.65,75.49 27.5,71.64 27.5,65.8 21.05,59.35 v1(20.75,59.35) ; v1(29.57,62) 25.14,62 21.34,58.2 v1(19.9,58.2) ; v1(31.85,123.14) 30.37,124.62 30.37,128.86 TP35.1 30.37,129.2 30.37,138.24 27.03,141.58 20.33,141.58 19.16,140.41 15.68,140.41 15.67,140.4 15.22,140.4 15.21,140.41 15.16,140.41 14.03,141.54 7.42,141.54 5.05,139.16 5.05,134 2.55,131.51 v1(2.55,125.57) 2.55,123.03 v1(2.99,122.58)
TL_COL2: length 207.5
  TOP w0.2: v1(7.7,93.5) 7.7,93.02 7.59,92.91 7.59,89.08 8.41,88.27 8.41,85.18 v1(5.89,82.67) ; SW16.1 v1(31.6,96.88) ; 7.34,120.45 7.64,120.74 ; 7.34,120.45 1.83,114.94 v1(1.83,112.64) ; 7.34,120.45 7.64,120.45 ; 7.64,120.74 7.64,120.45 ; 7.64,120.74 7.64,123.2 v1(7.46,123.37) ; v1(4.09,40.87) 6.96,40.87 10.76,37.08 v1(10.76,36.23) ; v1(29.85,45.86) 28.48,45.86 v1(28.27,46.07) ; SW19.1 v1(4.09,49.6) ; 7.64,120.45 7.64,120.43 8.14,119.92 8.44,119.62 8.44,119.24 v1(9.05,118.63) ; SW15.1 v1(19.13,49.6) ; SW18.1 v1(29.85,49.6) ; v1(12.73,122.49) 13.06,122.49 SW17.1
  BOTTOM w0.2: v1(9.05,118.63) 11.38,118.63 13.89,116.13 13.89,116.12 14.19,115.83 U1.20 ; v1(5.89,82.67) 4.72,81.5 4.72,68.23 6.6,66.35 6.6,61.73 3.3,58.43 3.3,50.38 v1(4.09,49.6) v1(4.09,40.87) ; v1(28.27,46.07) 24.74,49.6 v1(19.13,49.6) 17.93,49.6 16.82,48.48 16.82,39.79 17.74,38.86 17.74,37.14 16.84,36.23 v1(10.76,36.23) ; v1(12.73,122.49) 12.18,123.04 7.8,123.04 v1(7.46,123.37) ; v1(7.7,93.5) 7.7,94.97 1.99,100.68 1.99,112.48 1.83,112.63 v1(1.83,112.64) ; v1(29.85,45.86) v1(29.85,49.6) 31.6,51.35 v1(31.6,96.88)
TL_COL3: length 280.9
  TOP w0.2: v1(19.41,98.15) 19.25,98.15 SW23.1 ; v1(22.29,86.09) 21.95,86.43 v1(20.25,88.13) 16.91,88.13 16.35,87.57 v1(14.05,87.57) ; SW24.1 23.51,122.1 v1(24.03,122.62) ; v1(17.06,37.98) 17.62,37.98 SW22.1 18.69,37.5 v1(19.05,37.14) ; v1(30.06,33.86) 28.85,33.86 v1(28.45,34.26) ; v1(6.99,94.2) 6.99,93.72 6.99,93.71 6.99,93.22 7,93.22 7,88.7 7.77,87.93 v1(7.77,87.61) 7.77,85.42 v1(5.87,83.52) ; SW25.1 v1(30.8,37.55) ; SW26.1 v1(4.1,37.5)
  BOTTOM w0.2: v1(17.04,98) 17.04,95.29 20.55,91.78 20.55,88.43 v1(20.25,88.13) ; 19.85,101.13 19.85,108.3 18.22,109.94 18.22,111.28 18.27,111.33 U1.6 ; 19.85,101.13 19.85,101.19 ; 19.85,101.13 19.85,98.59 v1(19.41,98.15) ; v1(22.29,86.09) 23.25,85.13 23.25,75.32 27.1,71.47 27.1,65.97 21.06,59.92 18.57,59.92 14.28,55.64 14.28,41.33 17.06,38.55 v1(17.06,37.98) ; v1(14.05,87.57) 13.58,87.57 13.53,87.61 v1(7.77,87.61) ; v1(30.8,37.55) 30.06,36.82 v1(30.06,33.86) ; v1(5.87,83.52) 3.96,81.61 3.96,67.92 5.98,65.91 5.98,61.99 4.97,60.99 4.04,60.99 2.31,59.25 2.31,52.79 1.85,52.33 1.85,39.75 v1(4.1,37.5) ; v1(28.45,34.26) 25.57,37.14 v1(19.05,37.14) ; v1(24.03,122.62) 26.79,122.62 29.5,125.33 29.5,138.43 26.75,141.18 20.64,141.18 19.44,139.98 15.01,139.98 13.87,141.12 7.77,141.12 5.6,138.95 5.6,133.96 3.15,131.51 3.15,125.97 3.56,125.56 3.56,121.85 1.29,119.58 1.29,112.87 1.28,112.87 1.28,112.42 1.29,112.41 1.29,112.11 v1(1.44,111.96) 1.44,99.75 v1(6.99,94.2)
TL_COL4: length 142.9
  TOP w0.2: SW31.1 18.32,111.5 v1(18.77,111.05) ; v1(30.37,21.68) 28.76,21.68 v1(28.36,22.08) ; SW37.1 v1(4.11,25.4) ; v1(12.55,93) 15.13,93 16.64,94.51 19.39,94.51 21.61,96.72 21.61,99.36 v1(21.27,99.69) ; v1(4.11,21.83) 7.17,21.83 v1(10.54,25.2) ; SW30.1 v1(16.75,84.5)
  BOTTOM w0.2: v1(10.54,25.2) 17.42,25.2 17.62,25.4 v1(18.1,25.4) 18.89,25.4 20.93,23.36 27.08,23.36 v1(28.36,22.08) ; v1(21.27,99.69) 20.93,100.03 20.93,100.16 20.25,100.84 20.25,108.47 18.77,109.95 v1(18.77,111.05) U1.5 ; v1(30.8,25.4) 30.37,24.97 v1(30.37,21.68) ; v1(4.11,21.83) v1(4.11,25.4) 2.75,26.75 2.75,35.22 4.65,37.11 4.65,57.9 16.75,70 v1(16.75,84.5) 16.75,89.05 12.8,93 v1(12.55,93)
TL_COL5: length 234.5
  TOP w0.2: v1(4.14,17.01) 7.75,17.01 v1(10.51,14.25) ; v1(4.85,98.66) 4.6,98.42 SW36.1 ; SW38.1 v1(4.17,13.3) ; v1(2.02,81.96) 6.08,81.96 8.83,84.71 8.83,88.5 8.17,89.16 8.17,92.1 8.28,92.21 v1(8.28,94.35)
  BOTTOM w0.2: v1(2.02,81.96) 2.02,62.92 1.14,62.04 1.14,23.74 2.71,22.17 2.71,14.76 v1(4.17,13.3) 4.54,13.68 4.54,16.62 v1(4.14,17.01) ; v1(10.51,14.25) 17.15,14.25 v1(18.1,13.3) v1(30.8,13.3) 29.11,14.99 29.11,49.83 31.01,51.73 v1(31.01,73.47) 31.01,95.49 23.45,103.05 23.45,109.79 22.9,110.34 22.9,112.89 21.96,113.83 U1.45 ; v1(4.85,98.66) 8.28,95.23 v1(8.28,94.35)
TL_DM: length 36.8
  TOP w0.2: v1(13.4,89.8) 14.13,89.8 14.88,90.54 15.69,90.54 17.71,92.57 21.19,92.57 v1(21.91,93.28)
  BOTTOM w0.2: v1(21.91,93.28) 21.91,93.73 21.35,94.28 21.35,95.36 18.86,97.85 18.86,98.84 19.37,99.36 19.37,108.21 17.82,109.77 17.82,111.48 17.77,111.53 U1.7 ; v1(13.4,89.8) 13.34,89.86 R70.1
TL_DP: length 35.7
  TOP w0.2: v1(13.87,90.35) 14.48,90.96 15.51,90.96 17.54,93 20.52,93 v1(21.16,93.64)
  BOTTOM w0.2: v1(13.87,90.35) 13.8,90.42 8.21,90.42 7.85,90.79 R69.1 ; v1(21.16,93.64) 20.65,94.15 20.65,95.25 18.31,97.6 18.31,99.08 18.94,99.72 18.94,108.08 17.27,109.75 U1.8
TL_IRCONTROL: length 101
  TOP w0.2: v1(14.45,136.87) 14.93,136.87 16.27,135.53 19.7,135.53 21.27,133.96 22.43,133.96 v1(23.44,132.95) ; v1(22.51,94.71) 20.76,94.71 19.62,93.57 17.15,93.57 15.1,91.52 v1(13,91.52)
  BOTTOM w0.2: v1(14.45,136.87) 8.43,136.87 7,135.43 7,133.36 4.9,131.27 4.9,120.82 3.84,119.76 3.84,102.3 5.39,100.75 5.39,99.53 10.12,94.81 10.12,93.31 11.91,91.52 v1(13,91.52) ; v1(22.51,94.71) 22.51,95.19 22.67,95.35 22.67,100.01 21.05,101.63 21.05,108.8 19.77,110.08 U1.3
  BOTTOM w0.5: Q4.2 22.41,131.46 R11.1 22.41,132.45 R13.2 23.44,132.46 v1(23.44,132.95) R12.2
TL_IRIN: length 113.2
  TOP w0.2: v1(14.75,137.7) 16.49,135.96 19.98,135.96 21.36,134.58 v1(22.05,134.58) ; v1(22.41,88.44) 22,88.84 16.73,88.84 v1(16.11,88.23)
  BOTTOM w0.2: v1(14.75,137.7) 14.27,137.7 13.94,137.36 8.31,137.36 6.55,135.6 6.55,133.67 4.41,131.53 4.41,121.85 2.39,119.83 2.39,101.95 9.67,94.67 9.67,92.85 11.55,90.97 14.12,90.97 16.11,88.98 v1(16.11,88.23) ; v1(22.41,88.44) 22.41,88.92 22.16,89.16 22.16,92.08 22.74,92.66 22.74,93.65 21.78,94.61 21.78,96.68 21.53,96.94 TP36.1 21.53,98.39 22.04,98.9 22.04,100.07 20.65,101.46 20.65,101.51 20.65,108.63 19.37,109.92 19.37,111.23 19.27,111.33 U1.4
  BOTTOM w0.4: v1(22.05,134.58) 21.11,133.64 21.11,132.64 21.75,132 21.75,128.91 Q4.3
  BOTTOM w0.5: v1(22.05,134.58) 22.11,134.58 R10.1
TL_IROUT: length 35.4
  TOP w0.2: v1(9.08,119.38) 8.84,119.62 8.84,119.78 8.54,120.09 8.04,120.59 8.04,124.3 7.47,124.87 7.01,124.87 5.4,126.48 v1(3.86,126.48)
  BOTTOM w0.2: v1(3.86,126.48) 3.86,131.65 6,133.8 6,135.9 8,137.9 10.62,137.9 R9.1 ; U1.21 14.26,116.33 14.06,116.53 11.2,119.38 v1(9.08,119.38)
  BOTTOM w0.5: R9.1 10.85,139.53 10.84,139.55 R8.2
TL_LED1: length 16.1
  TOP w0.2: v1(21.32,127.17) 21.32,128.22 19.13,130.42 18.34,130.42 v1(17.72,131.04)
  BOTTOM w0.2: v1(21.32,127.17) 21.32,127.16 21.24,127.08 21.24,126.78 21.08,126.62 21.08,120.21 20.99,120.12 20.99,120.09 19.77,118.87 U1.34 ; R2.1 v1(17.72,131.04)
TL_LED2: length 15.7
  TOP w0.2: v1(22.12,127.03) 22.12,127.99 v1(18.88,131.23)
  BOTTOM w0.2: v1(18.88,131.23) 18.88,131.23 R1.1 ; v1(22.12,127.03) 21.72,126.63 21.66,126.63 21.48,126.46 21.48,119.94 20.27,118.73 U1.35
TL_ROW0: length 207.5
  TOP w0.2: v1(1.2,78.56) 5.67,78.56 7.77,76.46 v1(7.77,74.6) ; v1(19.73,23.36) 20.6,24.23 SW29.2 20.6,26.34 v1(18.96,27.98) ; v1(19.16,52) 20.6,50.56 SW15.2 ; v1(18.79,59.37) 20.6,61.18 SW8.2 ; v1(11.02,74.6) 12.44,76.01 14.67,76.01 15.95,74.73 SW1.2 ; v1(10.54,24.16) 7.53,21.15 2.65,21.15 v1(2.04,21.76) ; v1(19.65,15.51) 20.6,14.56 SW34.2 ; v1(18.95,40.07) 20.6,38.42 SW22.2
  BOTTOM w0.2: v1(18.76,34.99) 18.96,34.79 v1(18.96,27.98) ; v1(19.65,15.51) 19.65,15.99 19.73,16.08 v1(19.73,23.36) 19.26,23.36 19.1,23.21 16.53,23.21 15.58,24.16 v1(10.54,24.16) ; U1.47 21.64,112.83 21.97,112.5 21.97,112.15 21.65,111.83 21.65,110.46 22.65,109.46 22.65,102.3 24.65,100.3 24.65,76.55 27.9,73.3 27.9,65.63 21.02,58.75 20.3,58.75 19.68,59.37 v1(18.79,59.37) 18.79,52.36 v1(19.16,52) ; v1(2.04,21.76) 0.69,23.11 0.69,62.32 1.5,63.13 1.5,78.24 1.2,78.53 v1(1.2,78.56) ; v1(18.95,40.07) 18.95,46.24 v1(18.05,47.13) ; v1(11.02,74.6) v1(7.77,74.6)
TL_ROW1: length 222
  TOP w0.2: v1(31.89,124.56) 32.82,124.56 34.55,122.83 SW9.2 ; v1(25.32,77.47) 24.95,77.1 v1(20.8,77.1) ; SW2.2 33.3,134.37 v1(31.89,135.79) ; v1(7.09,75.73) 7.09,76.3 5.78,77.61 v1(0.69,77.61) ; v1(29.01,98.4) 29.35,98.74 29.35,99.03 30.76,100.44 32.79,100.44 34.1,99.13 SW16.2 v1(34.1,97.96) ; v1(20.6,85.1) SW30.2 20.6,84.49 v1(20.6,83.5) 20.6,83.2 20.15,82.76 19.82,82.76 18.91,81.84 17.56,81.84 16.79,82.6 v1(16.15,82.6)
  BOTTOM w0.2: v1(0.69,77.61) 0.69,78.08 0.49,78.29 0.49,112.08 0.48,112.08 0.48,113.2 0.49,113.21 0.49,131.24 3.82,134.58 3.82,139.31 6.89,142.38 27.57,142.38 31.89,138.07 v1(31.89,135.79) v1(31.89,124.56) ; v1(29.01,98.4) 23.85,103.56 23.85,109.96 23.3,110.51 23.3,113.05 22.03,114.33 U1.44 ; v1(25.32,77.47) 27.25,77.47 29.59,75.14 v1(29.59,74.4) ; v1(7.09,75.73) 9.27,75.73 v1(16.15,82.6) ; v1(34.1,97.96) 34.1,74.25 v1(34.52,73.83) ; v1(20.8,77.1) 20.8,82.82 20.6,83.02 v1(20.6,83.5) ; v1(20.6,85.1) 21,85.5 21,91.92 18.02,94.9 v1(18.02,95.58)
TL_ROW2: length 134.2
  TOP w0.2: v1(22.2,111.15) 20.95,111.15 SW31.2 ; v1(7.62,131.85) 7.95,132.19 7.95,133.45 SW3.2 ; v1(11.33,123.59) 12.13,124.38 14.46,124.38 15.95,122.89 ; v1(3.2,119.67) 5.05,119.67 6.65,121.26 SW10.2 6.65,123.64 v1(7.16,124.15) ; SW17.2 15.95,122.89 ; 15.95,122.89 15.95,123.05 14.48,124.52 12.33,124.52 10.82,123.02 10.82,122.58 ; v1(12.68,92.25) 15.03,92.25 16.89,94.11 19.57,94.11 20.96,95.5 23.36,95.5 25.2,93.66 v1(25.2,92.3) ; SW36.2 7.06,98.13 v1(7.06,98.77)
  BOTTOM w0.2: v1(24.6,124) 24.6,127.25 24.1,127.75 23.03,127.75 23.03,127.75 22.18,127.75 21.25,127.75 20.9,128.1 20.9,129.35 19.85,130.4 19.85,131.75 19.45,132.15 19.45,133.85 19.3,134 18.15,134 16.65,135.5 9.2,135.5 8.35,134.65 8.35,132.58 v1(7.62,131.85) 7.16,131.39 v1(7.16,124.15) 7.77,124.15 8.33,123.59 v1(11.33,123.59) ; v1(12.68,92.25) 12.11,92.25 10.78,93.59 10.78,95.06 v1(7.06,98.77) ; v1(4.84,100.48) 3.2,102.13 v1(3.2,119.67) ; U1.46 21.89,113.33 22.5,112.72 22.5,111.45 v1(22.2,111.15) 22.2,110.48 23.05,109.63 23.05,102.75 25.2,100.6 v1(25.2,92.3)
TL_ROW3: length 113.4
  TOP w0.2: v1(29.93,64.25) 32.05,64.25 33.1,63.2 SW11.2 33.1,61.27 31.45,59.63 v1(29.95,59.63) ; SW35.2 33.3,14.13 v1(31.68,15.75) ; v1(26.08,76.85) 25.04,75.81 25.04,75.01 v1(25.1,74.95) ; SW25.2 33.3,38.59 31.92,39.97 v1(31.08,39.97) ; v1(30.39,52.09) 31.88,52.09 33.3,50.66 SW18.2 ; v1(30.99,27.85) 31.68,27.85 33.3,26.23 SW32.2 33.3,24.5 31.85,23.05 v1(31.32,23.05)
  BOTTOM w0.2: U1.48 21.37,112.12 21.25,112 21.25,110.3 22.25,109.3 22.25,102.13 24.2,100.18 24.2,75.85 v1(25.1,74.95) ; v1(31.08,39.97) v1(31.08,47.15) ; v1(31.68,15.75) 31.68,22.7 v1(31.32,23.05) ; v1(26.08,76.85) 28.3,74.63 28.3,65.88 v1(29.93,64.25) ; v1(30.39,52.09) 30.39,59.18 v1(29.95,59.63) ; v1(30.99,27.85) v1(30.99,35.06)
TL_ROW4: length 153.7
  TOP w0.2: v1(4.19,35.3) 6.62,35.3 7.9,36.58 SW26.2 7.9,38.27 6.2,39.97 4.48,39.97 3.7,39.19 v1(3.23,39.19) ; 4.85,59.45 6.22,59.45 8.1,61.33 8.1,60.94 6.58,59.42 4.62,59.42 v1(4.02,60.01) ; SW38.2 7.9,14.25 6.27,15.89 4.45,15.89 v1(3.72,15.16) ; v1(5.25,64.4) 6.51,64.4 8.1,62.81 SW12.2 ; v1(3.39,24.24) 4.43,23.21 6.62,23.21 7.9,24.48 SW37.2 7.9,26.15 6.09,27.96 4.5,27.96 v1(3.83,27.3) ; v1(2.74,50.24) 2.74,50.71 3.32,51.3 3.49,51.3 4.32,52.13 6.2,52.13 7.9,50.43 SW19.2 ; v1(14.85,88.25) 15.87,89.27 23.06,89.27 23.17,89.39 v1(23.65,89.39)
  BOTTOM w0.2: v1(4.19,35.3) 4.19,27.65 v1(3.83,27.3) ; v1(7.59,63.72) 7.59,67.08 5.8,68.87 v1(5.8,75.68) 6.62,76.5 9.2,76.5 14.85,82.15 v1(14.85,88.25) ; v1(3.39,24.24) 3.39,15.96 3.72,15.63 v1(3.72,15.16) ; v1(3.23,39.19) 2.74,39.68 v1(2.74,50.24) 2.74,58.73 v1(4.02,60.01) ; v1(23.65,89.39) 23.65,94.92 23.67,94.95 23.67,100.14 21.85,101.97 21.85,109.13 20.77,110.21 U1.1
TL_RST: length 8.2
  BOTTOM w0.2: U1.36 20.77,118.6 22.03,119.86 C4.1
TL_SWS: length 6.8
  TOP w0.3: TP33.1 v1(17.97,107.82)
  BOTTOM w0.3: v1(17.97,107.82) TP34.1 16.77,109.03 U1.9
TL_VBUS: length 36.7
  TOP w0.5: v1(19.95,91.4) 19.99,91.36 v1(19.99,90.78) 19.03,89.82 15.64,89.82 15.58,89.76 15.58,89.76 14.85,89.04 v1(14.22,89.04) v1(13.6,89.04)
  BOTTOM w0.4: J3.1 5.36,89.37 6.14,88.59 C42.1
  BOTTOM w0.5: U5.1 15.02,103.78 14.75,104.05 14.1,104.05 13.4,104.05 13.12,103.77 U5.3 13.12,101.79 13.1,101.77 C39.1 13.1,100.1 16.06,97.14 16.06,95.12 19.34,91.85 19.51,91.85 v1(19.95,91.4) 19.95,91.4 19.95,90.81 v1(19.99,90.78) ; C42.1 13.15,88.59 v1(13.6,89.04) v1(14.22,89.04)
TL_VDD: length 548.5
  TOP w0.5: v1(8,102.56) v1(8,101.77) 8,101.39 8.67,100.72 8.67,95.95 9.07,95.56 9.07,91.87 v1(8.92,91.71) ; J36.2 19.62,102.62 TP21.1
  TOP w1: 22.07,68.76 22.07,69.43 v1(22.31,69.68) 20.72,69.68 v1(20.66,69.62) 21.52,68.76 ; 22.07,68.76 22.07,67.28 ; 22.07,68.76 21.52,68.76 ; 22.07,67.28 CD1.1 ; 22.07,67.28 21.52,67.83 ; 21.52,67.83 v1(20.66,68.68) 20.74,68.76 21.52,68.76 ; 21.52,67.83 21.52,68.76
  BOTTOM w0.2: 16.08,119.14 16.27,118.95 16.27,118.68 ; 16.08,119.14 16.01,119.21 15.63,119.21 ; 16.08,119.14 15.94,119 ; 15.77,118.75 15.62,118.9 ; 15.77,118.75 15.77,118.73 ; 15.77,118.75 15.77,118.83 ; 15.62,118.9 15.34,119.18 15.37,119.21 15.63,119.21 ; 15.62,118.9 15.62,118.88 15.77,118.73 ; 15.94,119 16.27,118.68 ; 15.94,119 15.77,118.83 ; 16.27,118.68 U1.27 ; 15.77,118.73 U1.26 ; 15.77,118.83 15.77,119.07 15.63,119.21
  BOTTOM w0.25: U1.15 13.55,113.33 12.64,112.41 C27.2
  BOTTOM w0.5: C16.1 21.77,71.21 ; C16.1 23.1,71.02 23.1,71.8 ; C16.1 22.53,71.23 ; C16.1 21.64,70.45 ; 21.77,71.21 21.86,71.21 22.2,71.55 ; 21.77,71.21 21.5,71.48 ; 21.77,71.21 21.64,71.07 21.64,70.45 ; 14.56,120.31 13.63,120.31 11.66,122.29 7.55,122.29 6.43,121.17 6.43,119.19 5.45,118.22 5.45,103.07 18.61,89.92 18.61,70.79 19.32,70.08 ; 14.56,120.31 C28.2 ; 14.56,120.31 14.88,120.31 15.03,120.46 ; 25.15,136.05 25.15,134.16 R12.1 ; 25.15,136.05 25.15,138.82 D4.A ; 25.15,136.05 C12.1 23.52,136.05 C26.1 23.1,136.02 ; 21.68,72.08 21.68,72.55 ; 21.68,72.08 22.2,71.55 ; 21.68,72.08 21.42,72.08 20.83,71.48 ; 21.68,72.08 22.16,72.08 ; 21.68,72.08 21.68,71.66 21.5,71.48 ; 21.68,72.55 22.16,72.08 ; 21.68,72.55 20.92,71.79 ; 21.68,72.55 21.55,72.68 21.55,92.2 19.75,94 19.75,95.25 17.75,97.25 17.75,101.55 17.59,101.71 J36.2 ; 20.61,71.48 20.49,71.48 20.18,71.79 ; 20.61,71.48 20.83,71.48 ; 20.61,71.48 20.92,71.79 ; 20.66,70.45 21.24,70.45 ; 20.66,70.45 20.35,70.45 ; 20.66,70.45 20.66,71.31 20.83,71.48 ; 21.24,70.45 21.24,71.22 21.5,71.48 ; 21.24,70.45 21.64,70.45 ; 20.35,70.45 20.18,70.63 20.18,71.3 ; 20.35,70.45 19.32,70.45 ; 20.92,71.79 20.18,71.79 ; 20.18,71.79 20.18,71.3 ; C7.2 15.03,120.46 ; 15.03,120.46 C28.2 ; C28.2 15.03,119.48 15.34,119.18 ; 20.18,71.3 19.95,71.08 ; 21.5,71.48 20.83,71.48 ; 23.1,72.14 22.99,72.14 22.7,72.44 22.7,72.08 ; 23.1,72.14 23.03,72.08 ; 23.1,72.14 23.1,71.8 ; 19.63,70.76 19.95,71.08 ; 19.63,70.76 19.32,70.45 ; 19.63,70.76 19.57,70.82 18.96,70.82 19.32,70.45 ; 19.95,71.08 19.51,71.52 19.51,90.27 v1(8,101.77) v1(8,102.56) 8.85,103.41 8.85,109.36 10.69,111.21 12.08,111.21 12.64,111.77 C27.2 ; 19.32,70.02 19.28,70.06 18.09,70.06 17.75,70.41 17.75,89.25 4.45,102.55 4.45,118.88 5.47,119.9 5.47,130.9 7.55,132.98 7.55,135.05 8.6,136.1 17.05,136.1 18.55,134.6 20.31,134.6 21.15,135.44 Q3.2 21.5,136.02 R10.2 ; 22.16,72.08 22.7,72.08 ; 22.53,71.23 22.2,71.55 ; 22.53,71.23 23.1,71.8 ; 23.1,136.02 R10.2 ; 23.1,136.02 23.04,136.08 23.04,136.51 ; R10.2 23.04,136.51 ; R7.2 23.05,136.51 23.04,136.51 ; 22.7,72.08 23.03,72.08 ; 23.03,72.08 22.5,71.55 22.2,71.55 ; R4.2 v1(8.92,91.71)
  BOTTOM w1: 22.31,68.8 21.68,69.44 ; 22.31,68.8 v1(22.31,69.68) 22.31,70.24 C16.1 ; 22.31,68.8 CD1.1 21.41,67.94 ; 21.68,69.44 20.66,70.45 v1(20.66,69.62) v1(20.66,68.68) ; 21.68,69.44 21.41,69.17 21.41,67.94 ; v1(20.66,68.68) 19.32,70.02 19.32,70.45 ; v1(20.66,68.68) 21.41,67.94
  BOTTOM w2: BT1.1 6.91,5.72 ; BT1.1 4.9,4.51 4.9,5.51 5.3,5.91 ; BT1.1 5.3,5.91 ; 6.91,5.72 7.17,5.98 ; 6.91,5.72 6.91,8.99 ; 8.9,10.97 8.9,54.21 21.85,67.16 21.85,67.49 ; 8.9,10.97 8.9,7.71 7.17,5.98 ; 8.9,10.97 7.17,9.25 ; 5.3,7.74 7.35,9.79 7.35,55.37 v1(20.66,68.68) ; 5.3,7.74 5.66,7.74 6.91,8.99 ; 5.3,7.74 5.3,6.9 ; 5.3,5.91 5.3,6.9 ; 5.3,6.9 6.05,7.65 6.05,56.77 19.29,70.02 19.32,70.02 ; 7.17,9.25 6.91,8.99 ; 7.17,9.25 7.17,5.98
TL_XC1: length 9.9
  BOTTOM w0.2: Y1.3 27.11,111.33 C19.2 27.11,112.15 27.11,112.39 26.73,112.78 25.35,112.78 24.2,113.93 23.8,113.93 22.67,115.06 22.67,115.46 21.8,116.33 U1.40
TL_XC2: length 12
  BOTTOM w0.2: U1.41 21.65,115.83 22.16,115.32 22.16,114.94 23.68,113.41 24.07,113.41 24.95,112.52 24.95,109.07 26.02,108 Y1.1 26.02,106.82 25.85,106.65 C20.2
N21000893: length 1.1
  TOP w0.5: D2.A 18.88,134.03 v1(18.88,133.43)
  BOTTOM w0.5: R1.2 v1(18.88,133.43)
N21007782: length 1.3
  TOP w0.5: D1.A 17.72,133.57 v1(17.72,133.46)
  BOTTOM w0.5: R2.2 v1(17.72,133.46)
N21036936: length 2.2
  TOP w0.2: v1(14.75,133.85) 14.54,133.85 U2.4
  BOTTOM w0.5: v1(14.75,133.85) 14.81,133.91 C13.1 R3.2
N21036981: length 0.9
  BOTTOM w0.2: C18.1 R17.2
N21036983: length 1.5
  TOP w0.2: U2.1 v1(11.7,134.2)
  BOTTOM w0.2: C18.2 11.49,133.99 v1(11.7,134.2)
N21081547: length 8.2
  BOTTOM w0.5: U5.5 15.02,107.15 C40.1 15.02,108.53 C41.1 15.66,108.54 16.3,107.9 16.3,106.77 16.99,106.08 16.99,105.76 J36.1
N21081898: length 2.4
  BOTTOM w0.2: J3.3 6.08,90.67 R69.2 6.19,91.7 R4.1
N21081900: length 1.5
  BOTTOM w0.2: R70.2 6.01,90.02 J3.2
N21088560: length 3.1
  BOTTOM w0.2: C10.2 12.57,116.8 14.04,115.33 U1.19
N21088582: length 5.1
  BOTTOM w0.3: L3.1 10.36,113.36 11.33,114.33 U1.17
N21088586: length 2.9
  BOTTOM w0.3: U1.16 13.23,113.83 12.74,113.34 12.73,113.36 L3.2
N21088616: length 2.6
  BOTTOM w0.3: U1.13 14.5,112.33 13.94,111.77 13.94,111.49 13.93,111.48 13.93,111.16 C8.2
N21092386: length 3.3
  BOTTOM w0.25: 22.18,117.33 U1.38
  BOTTOM w0.5: C33.1 24.7,117.35 23.81,117.35 23.81,117.35 C30.2 22.86,117.35 L4.2 22.83,117.33 22.18,117.33
N21092388: length 2.6
  BOTTOM w0.25: L4.1 22.04,118.32 21.83,118.11 21.82,118.11 21.54,117.83 U1.37
  BOTTOM w0.5: C31.1 22.83,119.23 L4.1
N21092398: length 1.8
  BOTTOM w0.5: L7.1 C32.2 C33.2
N21092424: length 34.1
  BOTTOM w0.5: 35.65,105.28 35.65,106.73 33.15,106.73 33.15,107.98 35.65,107.98 35.65,109.23 33.15,109.23 33.15,110.48 35.65,110.48 35.65,111.73 33.15,111.73 33.15,112.98 35.59,112.98 35.59,117.35 C35.2 C34.2 L7.2
N21108187: length 2.7
  BOTTOM w0.5: R7.1 20.6,137.5 20.6,137.5 D5.A
N21108227: length 16.3
  BOTTOM w0.5: R14.2 21.08,139.17 D4.C 21.19,139.73 22.09,140.63 25.7,140.63 26.18,140.15 26.18,133.32 25.31,132.45 R13.1
N21108333: length 1.3
  BOTTOM w0.5: Q2.1 11.85,138.13 R9.2
N21108349: length 3.1
  BOTTOM w0.5: Q2.3 15.37,139.16 R15.1 D5.C
N21108369: length 5.3
  TOP w0.5: v1(20.14,132.51) 21.16,132.51 v1(21.76,133.11)
  BOTTOM w0.5: R11.2 22.11,133.46 v1(21.76,133.11) ; Q4.1 20.74,131.9 v1(20.14,132.51) Q3.3
N21108379: length 5.7
  BOTTOM w0.4: 18.37,139.16 R15.2 18.12,138.87 ; 18.37,139.16 18.85,139.16 R14.1 ; 18.37,139.16 18.12,138.9 18.12,138.87 ; 18.12,138.87 18.12,136.2 18.65,135.67 Q3.1

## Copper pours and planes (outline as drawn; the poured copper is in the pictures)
GND on TOP: 4,0.3 1.38,1.38 0.3,4 0.3,144 0.8,145.2 2,145.7 10,145.7 10.49,145.49 10.7,145 10.7,143.8 11.08,142.88 12,142.5 24.2,142.5 25.12,142.88 25.5,143.8 25.5,145 25.71,145.49 26.2,145.7 34.2,145.7 35.4,145.2 35.9,144 35.9,124.52 30.65,119.27 30.65,116.54 30.6,100.4 35.9,100.4 35.9,4 34.82,1.38 32.2,0.3 ; 4 cut-outs
GND on BOTTOM: 4,0.3 1.38,1.38 0.3,4 0.3,144 0.8,145.2 2,145.7 10,145.7 10.49,145.49 10.7,145 10.7,143.8 11.08,142.88 12,142.5 24.2,142.5 25.12,142.88 25.5,143.8 25.5,145 25.71,145.49 26.2,145.7 34.2,145.7 35.4,145.2 35.9,144 35.9,124.51 30.65,119.26 30.65,118.11 30.64,118.11 22.25,118.11 22.25,116.58 30.65,116.58 30.65,100.4 35.9,100.4 35.9,4 34.82,1.38 32.2,0.3 ; 45 cut-outs

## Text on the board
Ref Des/Silkscreen Bottom: B7 | B6 | B5 | B4 | B1/TX | B0/RX | SWS | A2/UTX | A0/URX
User.Comments: AMJ-151029 | AMJ-160130 | +
Ref Des/Silkscreen Top: B6 | B5 | B7 | B4 | B1/TX | B0/RX | 32OUT | 32IN | GND | SWS | VDD | 2018-11-01 | C1T139A5_V1.4 | C0
COMPVAL_TYPE_BOTTOM: FIGURE | SIZE | 0.3 | 0.5 | 0.7 | 0.9 | 0.6 | 1.55x0.45 | 3.5x0.7 | DRILL CHART: TOP to BOTTOM | ALL UNITS ARE IN MILLIMETERS | PLATED | NON-PLATED | QTY | 547 | 2 | 12
BODY_CENTER: +
